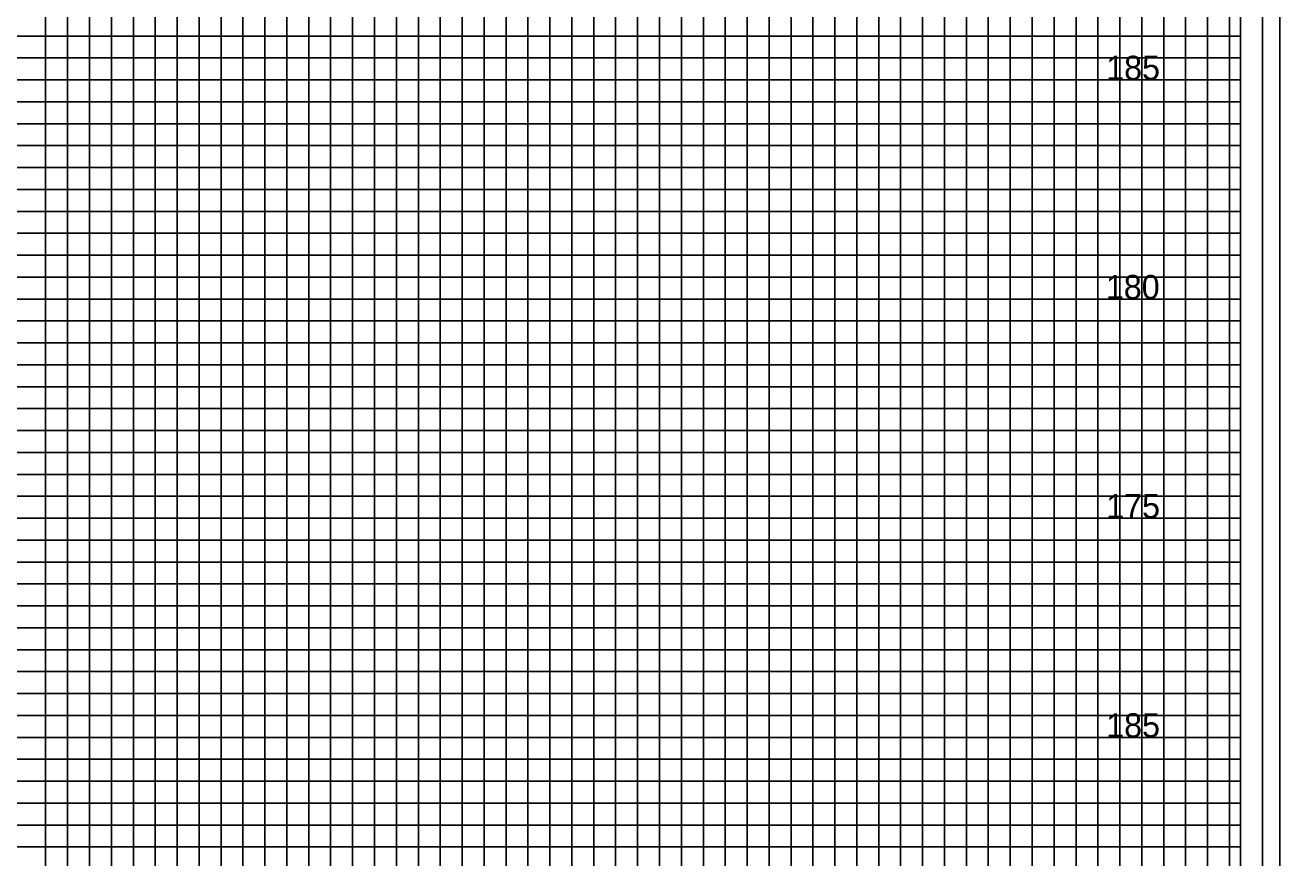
# Model space of a CAD drawing. Extents: x -4 to 103, y -2 to 138.
# Drawn here: x 74.78 to 103.4, y 32.25 to 51.25 of the extents above; entities that cross this region are included whole.
import ezdxf

# ---------------------------------------------------------------- set-up
doc = ezdxf.new("R2010")
doc.units = 0
for name, color, linetype in [('Old_Level_10', 7, 'Continuous'), ('Old_Level_4', 7, 'Continuous'), ('Old_Level_5', 7, 'Continuous'), ('Old_Level_8', 7, 'Continuous'), ('Prop XS Elevation Labels', 7, 'Continuous'), ('Prop XS EOT Tick Mark', 7, 'Continuous'), ('Prop XS Finish Grade', 7, 'Continuous')]:
    doc.layers.add(name, color=color, linetype=linetype)

msp = doc.modelspace()

# ---------------------------------------------------------------- linework, layer by layer
at = {"layer": 'Old_Level_10'}
for p, q in [((91.25, 0), (91.25, 63.425)), ((93.75, 0), (93.75, 63.425)), ((96.25, 0), (96.25, 63.425)), ((98.75, 0), (98.75, 63.425)), ((101.25, 0), (101.25, 63.425)), ((76.25, 0), (76.25, 62)), ((78.75, 0), (78.75, 62)), ((81.25, 0), (81.25, 62)), ((83.75, 0), (83.75, 62)), ((86.25, 0), (86.25, 62)), ((88.75, 0), (88.75, 62)), ((0, 50), (102.5, 50)), ((0, 47.5), (102.5, 47.5)), ((0, 45), (102.5, 45)), ((0, 42.5), (102.5, 42.5)), ((0, 40), (102.5, 40)), ((0, 37.5), (102.5, 37.5)), ((0, 35), (102.5, 35)), ((0, 32.5), (102.5, 32.5))]:
    msp.add_line(p, q, dxfattribs=at)
at = {"layer": 'Old_Level_4'}
msp.add_lwpolyline([(103, 66), (-2.8, 66), (-2.8, -1), (103, -1)], close=True, dxfattribs=at)
at = {"layer": 'Old_Level_5'}
msp.add_lwpolyline([(103.4, 67.4), (-3.5, 67.4), (-3.5, -2.425), (103.4, -2.425)], close=True, dxfattribs=at)
at = {"layer": 'Old_Level_8'}
for points in [[(91.25, 0), (91.25, 63.425), (93.75, 63.425), (93.75, 0)], [(96.25, 0), (96.25, 63.425), (98.75, 63.425), (98.75, 0)], [(101.25, 0), (101.25, 63.425)], [(76.25, 0), (76.25, 62), (78.75, 62), (78.75, 0)], [(81.25, 0), (81.25, 62), (83.75, 62), (83.75, 0)], [(86.25, 0), (86.25, 62), (88.75, 62), (88.75, 0)], [(0, 47.5), (102.5, 47.5), (102.5, 50), (0, 50)], [(0, 42.5), (102.5, 42.5), (102.5, 45), (0, 45)], [(0, 37.5), (102.5, 37.5), (102.5, 40), (0, 40)], [(0, 32.5), (102.5, 32.5), (102.5, 35), (0, 35)]]:
    msp.add_lwpolyline(points, dxfattribs=at)
at = {"layer": 'Prop XS Elevation Labels'}
msp.add_lwpolyline([(102.5, 65), (0, 65), (0, 0), (102.5, 0)], close=True, dxfattribs=at)
at = {"layer": 'Prop XS Finish Grade'}
for points in [[(90.25, 0), (90.25, 63.425), (90.75, 63.425), (90.75, 0)], [(91.75, 0), (91.75, 63.425), (92.25, 63.425), (92.25, 0)], [(92.75, 0), (92.75, 63.425), (93.25, 63.425), (93.25, 0)], [(94.25, 0), (94.25, 63.425), (94.75, 63.425), (94.75, 0)], [(95.25, 0), (95.25, 63.425), (95.75, 63.425), (95.75, 0)], [(96.75, 0), (96.75, 63.425), (97.25, 63.425), (97.25, 0)], [(97.75, 0), (97.75, 63.425), (98.25, 63.425), (98.25, 0)], [(99.25, 0), (99.25, 63.425), (99.75, 63.425), (99.75, 0)], [(100.25, 0), (100.25, 63.425)], [(100.25, 63.425), (100.75, 63.425), (100.75, 0), (101.75, 0), (101.75, 63.425), (102.25, 63.425), (102.25, 0)], [(75.25, 0), (75.25, 62), (75.75, 62), (75.75, 0)], [(76.75, 0), (76.75, 62), (77.25, 62), (77.25, 0)], [(77.75, 0), (77.75, 62), (78.25, 62), (78.25, 0)], [(79.25, 0), (79.25, 62), (79.75, 62), (79.75, 0)], [(80.25, 0), (80.25, 62), (80.75, 62), (80.75, 0)], [(81.75, 0), (81.75, 62), (82.25, 62), (82.25, 0)], [(82.75, 0), (82.75, 62), (83.25, 62), (83.25, 0)], [(84.25, 0), (84.25, 62), (84.75, 62), (84.75, 0)], [(85.25, 0), (85.25, 62), (85.75, 62), (85.75, 0)], [(86.75, 0), (86.75, 62), (87.25, 62), (87.25, 0)], [(87.75, 0), (87.75, 62), (88.25, 62), (88.25, 0)], [(89.25, 0), (89.25, 62), (89.75, 62), (89.75, 0)], [(0, 50.5), (102.5, 50.5), (102.5, 51), (0, 51)], [(0, 49), (102.5, 49), (102.5, 49.5), (0, 49.5)], [(0, 48), (102.5, 48), (102.5, 48.5), (0, 48.5)], [(0, 46.5), (102.5, 46.5), (102.5, 47), (0, 47)], [(0, 45.5), (102.5, 45.5), (102.5, 46), (0, 46)], [(0, 44), (102.5, 44), (102.5, 44.5), (0, 44.5)], [(0, 43), (102.5, 43), (102.5, 43.5), (0, 43.5)], [(0, 41.5), (102.5, 41.5), (102.5, 42), (0, 42)], [(0, 40.5), (102.5, 40.5), (102.5, 41), (0, 41)], [(0, 39), (102.5, 39), (102.5, 39.5), (0, 39.5)], [(0, 38), (102.5, 38), (102.5, 38.5), (0, 38.5)], [(0, 36.5), (102.5, 36.5), (102.5, 37), (0, 37)], [(0, 35.5), (102.5, 35.5), (102.5, 36), (0, 36)], [(0, 34), (102.5, 34), (102.5, 34.5), (0, 34.5)], [(0, 33), (102.5, 33), (102.5, 33.5), (0, 33.5)]]:
    msp.add_lwpolyline(points, dxfattribs=at)

# ---------------------------------------------------------------- texts
at = {"layer": 'Prop XS EOT Tick Mark'}
for s, p in [('185', (99.438, 50)), ('180', (99.43, 45)), ('175', (99.438, 40)), ('185', (99.438, 35))]:
    msp.add_text(s, height=0.55, dxfattribs=at).set_placement(p)

doc.saveas('drawing.dxf')
